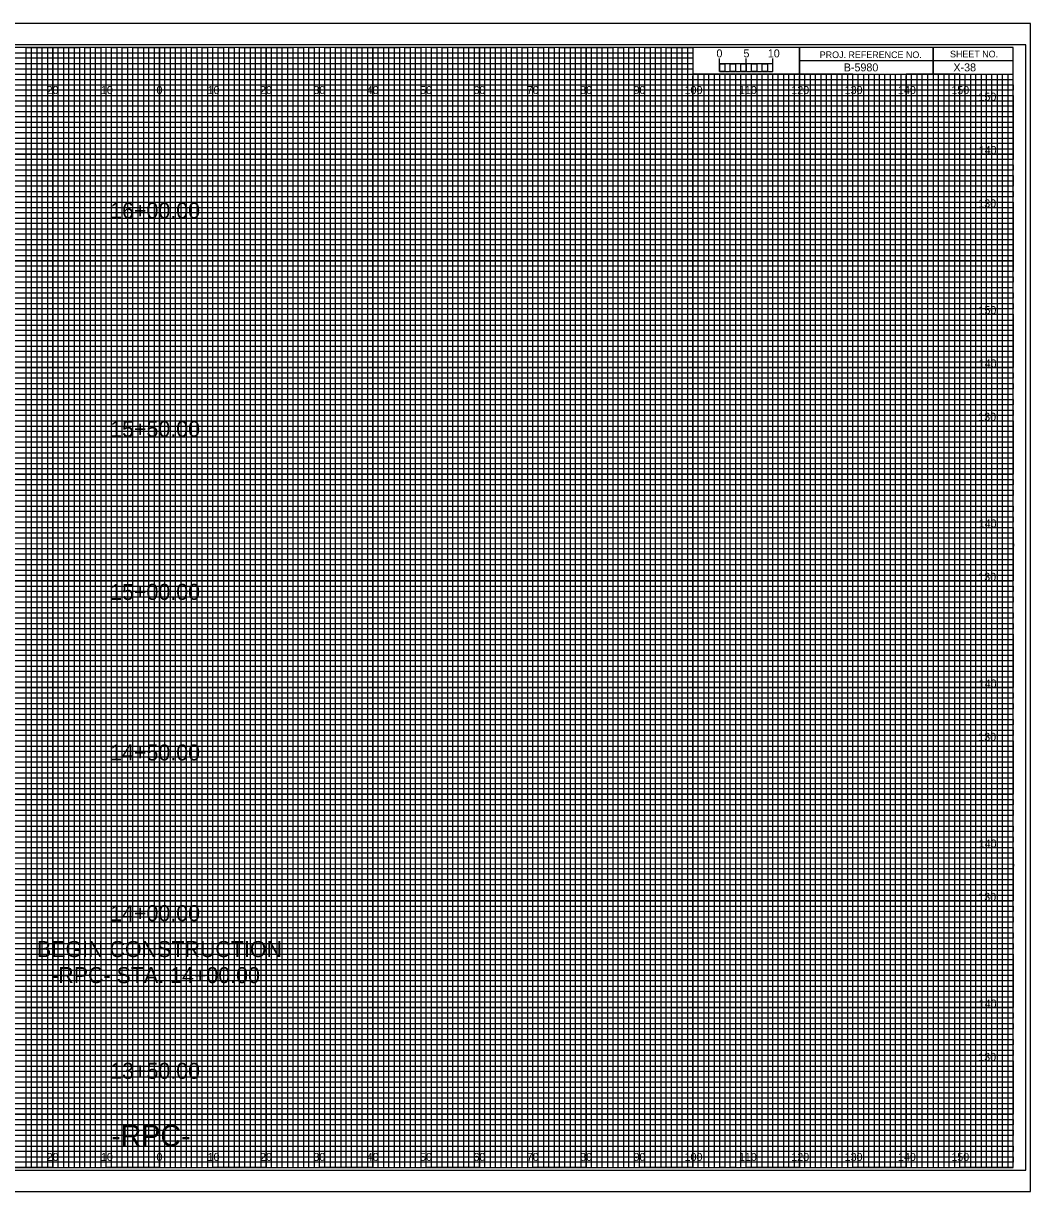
# Model space of a CAD drawing. Extents: x -13 to 323, y -5 to 874.
# Drawn here: x 134.5 to 323.3, y -4.5 to 214.5 of the extents above; entities that cross this region are included whole.
import ezdxf

# ---------------------------------------------------------------- set-up
doc = ezdxf.new("R2010")
doc.units = 0
for name, color, linetype in [('Exist Cross Section Cell', 7, 'Continuous'), ('Exist XS Center Line Elevation Label', 7, 'Continuous'), ('Exist XS Ground Line', 7, 'Continuous'), ('Prop CMT Conc Surface', 7, 'Continuous'), ('Prop CMT Concrete Structures', 7, 'Continuous'), ('Prop CMT Pvmt Course 1', 7, 'Continuous'), ('Prop CMT Pvmt Course 1 CG', 7, 'Continuous'), ('Prop CMT Pvmt Course 2', 7, 'Continuous'), ('Prop CMT Pvmt Course 3', 7, 'Continuous'), ('Prop CMT Pvmt Surface', 7, 'Continuous'), ('Prop CMT Pvmt Surface Shoulder', 7, 'Continuous'), ('Prop CMT Shld Paved Course 1', 7, 'Continuous'), ('Prop CMT Shld Paved Course 2', 7, 'Continuous'), ('Prop CMT Shld Paved Course 3', 7, 'Continuous'), ('Prop CMT Slope Grass', 7, 'Continuous'), ('Prop CMT Subgrade Earthwork', 7, 'Continuous'), ('Scratch_Level_1', 7, 'Continuous')]:
    doc.layers.add(name, color=color, linetype=linetype)

msp = doc.modelspace()

# ---------------------------------------------------------------- linework, layer by layer
at = {"layer": 'Exist XS Center Line Elevation Label'}
for points in [[(125, 0), (135, 0), (135, 210), (145, 210), (145, 0), (155, 0), (155, 210), (165, 210), (165, 0), (175, 0), (175, 210), (185, 210), (185, 0), (195, 0), (195, 210), (205, 210), (205, 0), (215, 0), (215, 210), (225, 210), (225, 0), (235, 0), (235, 210), (245, 210), (245, 0), (255, 0), (255, 210), (259.93, 210), (260, 210), (260, 205), (264.99, 205), (264.99, 0), (275, 0), (275, 205), (285, 205), (285, 0), (295, 0), (295, 205), (305, 205), (305, 0), (315, 0), (315, 205)], [(0, 205), (275, 205)], [(0, 185), (320, 185), (320, 195), (0, 195)], [(0, 165), (320, 165), (320, 175), (0, 175)], [(0, 145), (320, 145), (320, 155), (0, 155)], [(0, 125), (320, 125), (320, 135), (0, 135)], [(0, 105), (320, 105), (320, 115), (0, 115)], [(0, 85), (320, 85), (320, 95), (0, 95)], [(0, 65), (320, 65), (320, 75), (0, 75)], [(0, 45), (320, 45), (320, 55), (0, 55)], [(0, 25), (320, 25), (320, 35), (0, 35)], [(0, 5), (320, 5), (320, 15), (0, 15)]]:
    msp.add_lwpolyline(points, dxfattribs=at)
at = {"layer": 'Exist XS Ground Line'}
for p, q in [((150, 210), (140, 210)), ((140, 210), (140, 0)), ((150, 0), (150, 210)), ((170, 210), (160, 210)), ((160, 210), (160, 0)), ((170, 0), (170, 210)), ((190, 210), (180, 210)), ((180, 210), (180, 0)), ((190, 0), (190, 210)), ((210, 210), (200, 210)), ((200, 210), (200, 0)), ((210, 0), (210, 210)), ((230, 210), (220, 210)), ((220, 210), (220, 0)), ((230, 0), (230, 210)), ((250, 210), (240, 210)), ((240, 210), (240, 0)), ((250, 0), (250, 210)), ((260, 210), (260, 0)), ((270, 0), (270, 205)), ((290, 205), (280, 205)), ((280, 205), (280, 0)), ((290, 0), (290, 205)), ((310, 205), (300, 205)), ((300, 205), (300, 0)), ((310, 0), (310, 205)), ((140, 0), (130, 0)), ((160, 0), (150, 0)), ((180, 0), (170, 0)), ((200, 0), (190, 0)), ((220, 0), (210, 0)), ((240, 0), (230, 0)), ((260, 0), (250, 0)), ((280, 0), (270, 0)), ((300, 0), (290, 0)), ((320, 0), (310, 0)), ((320, 0), (320, 0))]:
    msp.add_line(p, q, dxfattribs=at)
for points in [[(0, 200), (320, 200), (320, 190), (0, 190)], [(0, 180), (320, 180), (320, 170), (0, 170)], [(0, 160), (320, 160), (320, 150), (0, 150)], [(0, 140), (320, 140), (320, 130), (0, 130)], [(0, 120), (320, 120), (320, 110), (0, 110)], [(0, 100), (320, 100), (320, 90), (0, 90)], [(0, 80), (320, 80), (320, 70), (0, 70)], [(0, 60), (320, 60), (320, 50), (0, 50)], [(0, 40), (320, 40), (320, 30), (0, 30)], [(0, 20), (320, 20), (320, 10), (0, 10)]]:
    msp.add_lwpolyline(points, dxfattribs=at)
at = {"layer": 'Prop CMT Pvmt Course 2'}
for p, q in [((265, 205.49), (265, 207.9)), ((265, 206.9), (265, 207.9)), ((270, 205.49), (270, 207.9)), ((275, 205.49), (275, 207.9)), ((275, 206.9), (275, 207.9))]:
    msp.add_line(p, q, dxfattribs=at)
for points in [[(275, 206.9), (265, 206.9), (265, 205.49), (275, 205.49)], [(265, 206.9), (266, 206.9), (266, 205.49), (265, 205.49)], [(267, 206.9), (268, 206.9), (268, 205.49), (267, 205.49)], [(269, 206.9), (270, 206.9), (270, 205.49), (269, 205.49)], [(271, 206.9), (272, 206.9), (272, 205.49), (271, 205.49)], [(273, 206.9), (274, 206.9), (274, 205.49), (273, 205.49)]]:
    msp.add_lwpolyline(points, close=True, dxfattribs=at)
at = {"layer": 'Prop CMT Pvmt Course 3'}
msp.add_lwpolyline([(-13.4, -4.5), (323.3, -4.5), (323.3, 214.5), (-13.4, 214.5)], close=True, dxfattribs=at)
at = {"layer": 'Prop CMT Pvmt Surface'}
for p, q in [((140, 0), (140, 210)), ((150, 0), (150, 210)), ((160, 0), (160, 210)), ((170, 0), (170, 210)), ((180, 0), (180, 210)), ((190, 0), (190, 210)), ((200, 0), (200, 210)), ((210, 0), (210, 210)), ((220, 0), (220, 210)), ((230, 0), (230, 210)), ((240, 0), (240, 210)), ((250, 0), (250, 210)), ((260, 0), (260, 204.69)), ((270, 0), (270, 204.69)), ((280, 0), (280, 204.69)), ((290, 0), (290, 204.69)), ((300, 0), (300, 204.69)), ((310, 0), (310, 204.69)), ((0, 200), (320, 200)), ((0, 190), (320, 190)), ((0, 180), (320, 180)), ((0, 170), (320, 170)), ((0, 160), (320, 160)), ((0, 150), (320, 150)), ((0, 140), (320, 140)), ((0, 130), (320, 130)), ((0, 120), (320, 120)), ((0, 110), (320, 110)), ((0, 100), (320, 100)), ((0, 90), (320, 90)), ((0, 80), (320, 80)), ((0, 70), (320, 70)), ((0, 60), (320, 60)), ((0, 50), (320, 50)), ((0, 40), (320, 40)), ((0, 30), (320, 30)), ((0, 20), (320, 20)), ((0, 10), (320, 10))]:
    msp.add_line(p, q, dxfattribs=at)
at = {"layer": 'Prop CMT Pvmt Surface Shoulder'}
for p, q in [((323.3, 214.5), (-13.4, 214.5)), ((-13.4, -4.5), (323.3, -4.5))]:
    msp.add_line(p, q, dxfattribs=at)
at = {"layer": 'Prop CMT Shld Paved Course 1'}
for p, q in [((0, 209), (260, 209)), ((260, 209), (260, 207.98)), ((260, 207.98), (0, 207.98)), ((0, 207), (260, 207)), ((260, 205.89), (0, 205.89)), ((260, 207), (260, 205.89)), ((0, 204), (320, 204))]:
    msp.add_line(p, q, dxfattribs=at)
for points in [[(0, 203), (270, 203), (320, 203), (320, 202), (0, 202)], [(0, 201), (320, 201), (320, 199), (0, 199)], [(0, 198), (320, 198), (320, 197), (0, 196.98)], [(0, 196), (320, 196), (320, 194), (0, 194)], [(0, 193), (320, 193), (320, 192), (0, 192)], [(0, 191), (320, 191), (320, 189), (0, 189)], [(0, 188), (320, 188), (320, 187), (0, 187)], [(0, 186), (320, 186), (320, 184), (0, 184)], [(0, 183), (320, 183), (320, 182), (0, 182)], [(0, 181), (320, 181), (320, 179), (0, 179)], [(0, 178), (320, 178), (320, 177), (0, 177)], [(0, 176), (320, 176), (320, 173.95), (320, 173), (320, 172), (0, 172)], [(0, 174), (320, 174), (320, 173), (0, 173)], [(0, 171), (320, 171), (320, 169), (0, 169.03)], [(0, 169.03), (320, 169), (320, 168), (0, 168)], [(0, 167), (320, 167), (320, 166), (0, 166)], [(0, 164), (320, 164), (320, 163), (0, 163)], [(0, 162), (320, 162), (320, 161), (0, 161)], [(-0.07, 158.89), (320, 158.89), (320, 157.88), (-0.07, 157.88)], [(0, 157), (320, 157), (320, 156), (0, 156)], [(0, 154), (320, 154), (320, 153), (0, 153)], [(0, 152), (320, 152), (320, 151), (0, 151)], [(0, 149), (320, 149), (320, 148), (0, 148)], [(0, 147), (320, 147), (320, 146), (0, 146)], [(0, 144), (320, 144), (320, 143), (0, 143)], [(0, 142), (320, 142), (320, 141), (0, 141)], [(0, 139), (320, 139), (319.99, 137.98), (0, 138)], [(0, 137), (320, 137), (320, 136), (0, 136)], [(0, 134), (320, 134), (320, 133), (0, 133)], [(0, 132), (320, 132), (320, 131), (0, 131)], [(0, 129), (320, 129), (320, 128), (0, 128)], [(0, 127), (320, 127), (320, 126), (0, 126)], [(0, 124), (320, 124), (320, 123), (0, 123)], [(0, 122), (320, 122), (320, 121), (0, 121)], [(0, 119), (320, 119), (320, 118), (0, 118)], [(0, 116.99), (320.07, 116.91), (320, 116), (0, 116)], [(0, 114), (320, 114), (320, 113), (0, 113)], [(0, 112), (320, 112), (320, 111), (0, 111)], [(0, 109), (320, 109), (320, 108), (0, 108)], [(0, 107), (320, 107), (320, 106), (0, 106)], [(0, 104), (320, 104), (320, 103), (0, 103)], [(0, 102), (320, 102), (320, 101), (0, 101)], [(0, 99), (320, 99), (320, 98), (0, 98)], [(0, 97), (320, 97), (320, 96), (0, 96)], [(0, 94), (320, 94), (320, 93), (0, 93)], [(0, 92), (320, 92), (320, 91), (0, 91)], [(0, 89), (320, 89), (320, 88), (0, 88)], [(0, 87), (320, 87), (320, 86), (0, 86)], [(0, 84), (320, 84), (320, 83), (0, 83)], [(0, 82), (320, 82), (320, 81), (0, 81)], [(0, 79), (320, 79), (319.99, 77.98), (0, 78)], [(0, 77), (320, 77), (320, 76), (0, 76)], [(0, 74), (320, 74), (320, 73), (0, 73)], [(0, 72), (320, 72), (320, 71), (0, 71)], [(0, 69), (320, 69), (320, 68), (0, 68)], [(0, 67), (320, 67), (320, 66), (0, 66)], [(0, 64), (320, 64), (320, 63), (0, 63)], [(0, 62), (320, 62), (320, 61), (0, 61)], [(0, 59), (320, 59), (320, 58), (0, 58)], [(0, 56.99), (320.07, 56.91), (320, 56), (0, 56)], [(0, 54), (320, 54), (320, 53), (0, 53)], [(0, 52), (320, 52), (320, 51), (0, 51)], [(0, 49), (320, 49), (320, 48), (0, 48)], [(0, 47), (320, 47), (320, 46), (0, 46)], [(0, 44), (320, 44), (320, 43), (0, 43)], [(0, 42), (320, 42), (320, 41), (0, 41)], [(0, 39), (320, 39), (320, 38), (0, 38)], [(0, 37), (320, 37), (320, 36), (0, 36)], [(0, 34), (320, 34), (320, 33), (0, 33)], [(0, 32), (320, 32), (320, 31), (0, 31)], [(0, 29), (320, 29), (320, 28), (0, 28)], [(0, 27), (320, 27), (320, 26), (0, 26)], [(0, 24), (320, 24), (320, 23), (0, 23)], [(0, 22), (320, 22), (320, 21), (0, 21)], [(0, 19), (320, 19), (320, 18), (0, 18)], [(0, 17), (320, 17), (320, 16), (0, 16)], [(0, 14), (320, 14), (320, 13), (0, 13)], [(0, 12), (320, 12), (320, 11), (0, 11)], [(0, 9), (320, 9), (320, 8), (0, 8)], [(0, 7), (320, 7), (320, 6), (0, 6)], [(0, 4), (320, 4), (320, 3), (0, 3)], [(0, 2), (320, 2), (320, 1), (0, 1)]]:
    msp.add_lwpolyline(points, dxfattribs=at)
at = {"layer": 'Prop CMT Shld Paved Course 2'}
for p, q in [((305, 210), (305, 205)), ((305, 205), (305, 210)), ((280, 207.5), (280, 205)), ((320, 207.49), (280, 207.49)), ((280, 205), (320, 205))]:
    msp.add_line(p, q, dxfattribs=at)
for points in [[(320, 210), (0, 210), (0, 0), (320, 0)], [(280, 210), (260, 210), (260, 205.03), (280, 205.03)], [(320, 210), (280, 210), (280, 205), (320, 205)]]:
    msp.add_lwpolyline(points, close=True, dxfattribs=at)
at = {"layer": 'Prop CMT Shld Paved Course 3'}
for p, q in [((267, 205), (266.01, 205)), ((266.01, 205), (266.01, 0)), ((267, 0), (267, 205)), ((269, 205), (268, 205)), ((268, 205), (268, 0)), ((269, 0), (269, 205)), ((266.01, 0), (265, 0)), ((268, 0), (267, 0))]:
    msp.add_line(p, q, dxfattribs=at)
for points in [[(135, 0), (136, 0), (136, 210), (137, 210), (137, 0)], [(137, 0), (138, 0), (138, 210), (139, 210), (139, 0)], [(140, 0), (141, 0), (141, 210), (142, 210), (142, 0)], [(142, 0), (143, 0), (143, 210), (144, 210), (144, 0)], [(145, 0), (146, 0), (146, 210), (147, 210), (147, 0)], [(147, 0), (148, 0), (148, 210), (149, 210), (149, 0)], [(150, 0), (151, 0), (151, 210), (152, 210), (152, 0)], [(152, 0), (153, 0), (153, 210), (154, 210), (154, 0)], [(155, 0), (156, 0), (156, 210), (157, 210), (157, 0)], [(157, 0), (158, 0), (158, 210), (159, 210), (159, 0)], [(160, 0), (161, 0), (161, 210), (162, 210), (162, 0)], [(162, 0), (163, 0), (163, 210), (164, 210), (164, 0)], [(165, 0), (166, 0), (166, 210), (167, 210), (167, 0)], [(167, 0), (168, 0), (168, 210), (169, 210), (169, 0)], [(170, 0), (171, 0), (171, 210), (172, 210), (172, 0)], [(172, 0), (173, 0), (173, 210), (174, 210), (174, 0)], [(175, 0), (176, 0), (176, 210), (177, 210), (177, 0)], [(177, 0), (178, 0), (178, 210), (179, 210), (179, 0)], [(180, 0), (181, 0), (181, 210), (182, 210), (182, 0)], [(182, 0), (183, 0), (183, 210), (184, 210), (184, 0)], [(185, 0), (186, 0), (186, 210), (187, 210), (187, 0)], [(187, 0), (188, 0), (188, 210), (189, 210), (189, 0)], [(190, 0), (191, 0), (191, 210), (192, 210), (192, 0)], [(192, 0), (193, 0), (193, 210), (194, 210), (194, 0)], [(195, 0), (196, 0), (196, 210), (197, 210), (197, 0)], [(197, 0), (198, 0), (198, 210), (199, 210), (199, 0)], [(200, 0), (201, 0), (201, 210), (202, 210), (202, 0)], [(202, 0), (203, 0), (203, 210), (204, 210), (204, 0)], [(205, 0), (206, 0), (206, 210), (207, 210), (207, 0)], [(207, 0), (208, 0), (208, 210), (209, 210), (209, 0)], [(210, 0), (211, 0), (211, 210), (212, 210), (212, 0)], [(212, 0), (213, 0), (213, 210), (214, 210), (214, 0)], [(215, 0), (216, 0), (216, 210), (217, 210), (217, 0)], [(217, 0), (218, 0), (218, 210), (219, 210), (219, 0)], [(220, 0), (221, 0), (221, 210), (222, 210), (222, 0)], [(222, 0), (223, 0), (223, 210), (224, 210), (224, 0)], [(225, 0), (226, 0), (226, 210), (227, 210), (227, 0)], [(227, 0), (228, 0), (228, 210), (229, 210), (229, 0)], [(230, 0), (231, 0), (231, 210), (232, 210), (232, 0)], [(232, 0), (233, 0), (233, 210), (234, 210), (234, 0)], [(235, 0), (236, 0), (236, 210), (237, 210), (237, 0)], [(237, 0), (238, 0), (238, 210), (239, 210), (239, 0)], [(240, 0), (241, 0), (241, 210), (242, 210), (242, 0)], [(242, 0), (243, 0), (243, 210), (244, 210), (244, 0)], [(245, 0), (246, 0), (246, 210), (247, 210), (247, 0)], [(247, 0), (248, 0), (248, 210), (249, 210), (249, 0)], [(250, 0), (251, 0), (251, 210), (252, 210), (252, 0)], [(252, 0), (253, 0), (253, 210), (254, 210), (254, 0)], [(255, 0), (256, 0), (256, 210), (257, 210), (257, 0)], [(257, 0), (258, 0), (258, 210), (259, 210), (259, 0)], [(260, 0), (261, 0), (261, 205), (262.02, 205), (262.02, 0)], [(262, 0), (263, 0), (263, 205), (263.99, 205), (263.99, 0)], [(270, 0), (270.98, 0), (270.98, 205), (272, 205), (272, 0)], [(272, 0), (273, 0), (273, 205), (274.05, 205), (274.05, 0)], [(275, 0), (276, 0), (276, 205), (277, 205), (277, 0)], [(277, 0), (278, 0), (278, 205), (279, 205), (279, 0)], [(280, 0), (281, 0), (281, 205), (282, 205), (282, 0)], [(282, 0), (283, 0), (283, 205), (284, 205), (284, 0)], [(285, 0), (286, 0), (286, 205), (287, 205), (287, 0)], [(287, 0), (288, 0), (288, 205), (289, 205), (289, 0)], [(290, 0), (291, 0), (291, 205), (292, 205), (292, 0)], [(292, 0), (293, 0), (293, 205), (294, 205), (294, 0)], [(295, 0), (296, 0), (296, 205), (297, 205), (297, 0)], [(297, 0), (298, 0), (298, 205), (299, 205), (299, 0)], [(300, 0), (301, 0), (301, 205), (302, 205), (302, 0)], [(302, 0), (303, 0), (303, 205), (304, 205), (304, 0)], [(305, 0), (306, 0), (306, 205), (307, 205), (307, 0)], [(307, 0), (308, 0), (308, 205), (309, 205), (309, 0)], [(310, 0), (311, 0), (311, 205), (312, 205), (312, 0)], [(312, 0), (313, 0), (313, 205), (314, 205), (314, 0)], [(315, 0), (316, 0), (316, 205), (317, 205), (317, 0)], [(317, 0), (318, 0), (318, 205), (319, 205), (319, 0)]]:
    msp.add_lwpolyline(points, dxfattribs=at)
at = {"layer": 'Prop CMT Subgrade Earthwork'}
msp.add_lwpolyline([(-10.8, -0.5), (322.4, -0.5), (322.4, 210.5), (-10.8, 210.5)], close=True, dxfattribs=at)

# ---------------------------------------------------------------- texts
at = {"layer": 'Exist Cross Section Cell'}
for s, p in [('20', (138.86, 201.25)), ('10', (149.04, 201.25)), ('0', (159.45, 201.25)), ('0', (159.45, 201.25)), ('10', (169.04, 201.25)), ('20', (178.86, 201.25)), ('30', (188.86, 201.25)), ('40', (198.86, 201.25)), ('50', (208.86, 201.25)), ('60', (218.86, 201.25)), ('70', (228.86, 201.25)), ('80', (238.86, 201.25)), ('90', (248.86, 201.25)), ('100', (258.44, 201.25)), ('110', (268.62, 201.25)), ('120', (278.44, 201.25)), ('130', (288.44, 201.25)), ('140', (298.44, 201.25)), ('150', (308.44, 201.25)), ('20', (138.86, 1.25)), ('10', (149.04, 1.25)), ('0', (159.45, 1.25)), ('0', (159.45, 1.25)), ('10', (169.04, 1.25)), ('20', (178.86, 1.25)), ('30', (188.86, 1.25)), ('40', (198.86, 1.25)), ('50', (208.86, 1.25)), ('60', (218.86, 1.25)), ('70', (228.86, 1.25)), ('80', (238.86, 1.25)), ('90', (248.86, 1.25)), ('100', (258.44, 1.25)), ('110', (268.62, 1.25)), ('120', (278.44, 1.25)), ('130', (288.44, 1.25)), ('140', (298.44, 1.25)), ('150', (308.44, 1.25))]:
    msp.add_text(s, height=1.5, dxfattribs=at).set_placement(p)
at = {"layer": 'Prop CMT Conc Surface'}
for s, p in [('5', (269.47, 208.12)), ('10', (274.04, 208.12))]:
    msp.add_text(s, height=1.5, dxfattribs=at).set_placement(p)
at = {"layer": 'Prop CMT Concrete Structures'}
msp.add_text('B-5980', height=1.5, dxfattribs=at).set_placement((288.28, 205.5))
at = {"layer": 'Prop CMT Pvmt Course 1'}
for s, p in [('150', (313.52, 200)), ('140', (313.57, 190)), ('130', (313.49, 180)), ('150', (313.52, 160)), ('140', (313.57, 150)), ('130', (313.49, 140)), ('140', (313.57, 120)), ('130', (313.49, 110)), ('140', (313.57, 90)), ('130', (313.49, 80)), ('140', (313.57, 60)), ('130', (313.49, 50)), ('140', (313.57, 30)), ('130', (313.49, 20))]:
    msp.add_text(s, height=1.5, dxfattribs=at).set_placement(p)
at = {"layer": 'Prop CMT Pvmt Course 1 CG'}
msp.add_text('-RPC-', height=4, dxfattribs=at).set_placement((150.97, 4))
at = {"layer": 'Prop CMT Pvmt Course 2'}
msp.add_text('0', height=1.5, dxfattribs=at).set_placement((264.41, 208.12))
at = {"layer": 'Prop CMT Shld Paved Course 2'}
for s, p in [('PROJ. REFERENCE NO.', (283.77, 207.99)), ('SHEET NO.', (308.19, 208.12))]:
    msp.add_text(s, height=1.25, dxfattribs=at).set_placement(p)
at = {"layer": 'Prop CMT Slope Grass'}
for s, p in [('16+00.00', (150.77, 177.92)), ('15+50.00', (150.77, 136.97)), ('15+00.00', (150.77, 106.43)), ('14+50.00', (150.77, 76.33)), ('14+00.00', (150.77, 46.2)), ('BEGIN CONSTRUCTION', (137.05, 39.47)), ('-RPC- STA. 14+00.00', (139.71, 34.59)), ('13+50.00', (150.77, 16.65))]:
    msp.add_text(s, height=3, dxfattribs=at).set_placement(p)
at = {"layer": 'Scratch_Level_1'}
msp.add_text('X-38', height=1.5, dxfattribs=at).set_placement((308.83, 205.5))

doc.saveas('drawing.dxf')
